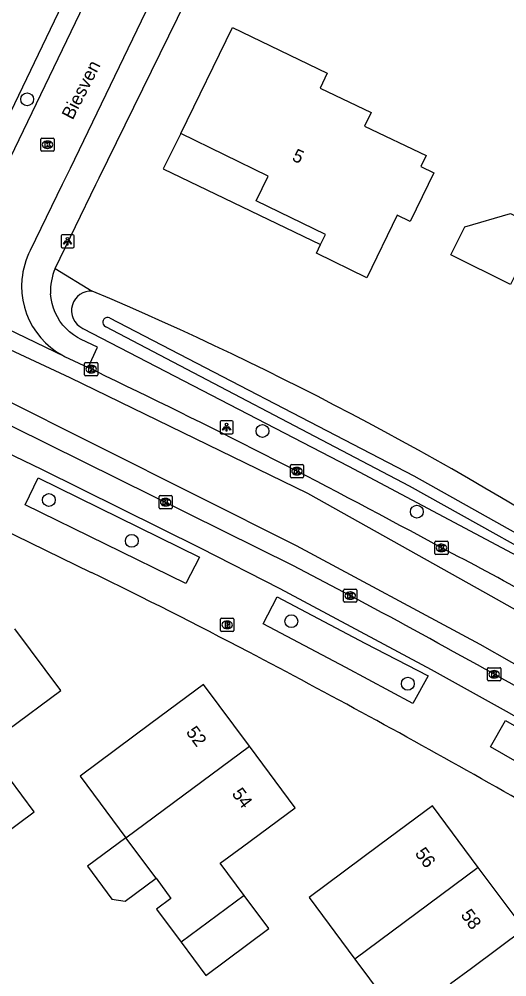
# Model space of a CAD drawing. Extents: x 163427 to 164190, y 380331 to 381641.
# Drawn here: x 163745.4 to 163782.5, y 381439.7 to 381512.6 of the extents above; entities that cross this region are included whole.
import ezdxf

# ---------------------------------------------------------------- set-up
doc = ezdxf.new("R2010")
doc.units = 0
for name, color, linetype in [('IMGEO_Boom', 7, 'Continuous'), ('IMGEO_Brandkraan', 7, 'Continuous'), ('IMGEO_Erf', 7, 'Continuous'), ('IMGEO_Groenvoorziening', 7, 'Continuous'), ('IMGEO_Kolk', 7, 'Continuous'), ('IMGEO_Lichtpunt', 7, 'Continuous'), ('IMGEO_Openbare_ruimte_label', 7, 'Continuous'), ('IMGEO_Pand', 7, 'Continuous'), ('IMGEO_Pand_nummerreeks', 7, 'Continuous'), ('IMGEO_Pand_overbouw', 7, 'Continuous'), ('IMGEO_Rijbaan_lokaal_gesloten', 7, 'Continuous'), ('IMGEO_Rijbaan_lokaal_open', 7, 'Continuous'), ('IMGEO_Voetpad_open', 7, 'Continuous'), ('IMGEO_Waterloop', 7, 'Continuous')]:
    doc.layers.add(name, color=color, linetype=linetype)

msp = doc.modelspace()

# ---------------------------------------------------------------- linework, layer by layer
at = {"layer": 'IMGEO_Boom'}
for centre in [(163745.966, 381506.482), (163763.886, 381481.228), (163747.622, 381475.986), (163775.647, 381475.092), (163753.933, 381472.871), (163766.089, 381466.756), (163774.959, 381461.993)]:
    msp.add_circle(centre, 0.489, dxfattribs=at)
at = {"layer": 'IMGEO_Brandkraan'}
for p, q in [((163760.702, 381466.052), (163760.702, 381466.904)), ((163760.777, 381466.978), (163761.629, 381466.978)), ((163761.19, 381466.758), (163761.215, 381466.758)), ((163761.703, 381466.904), (163761.703, 381466.052)), ((163761.629, 381465.978), (163760.777, 381465.978)), ((163761.213, 381466.198), (163761.188, 381466.198))]:
    msp.add_line(p, q, dxfattribs=at)
for points in [[(163760.702, 381466.052), (163760.702, 381466.904)], [(163760.777, 381466.978), (163761.629, 381466.978)], [(163761.05, 381466.678), (163761.05, 381466.278), (163761.263, 381466.278)], [(163761.281, 381466.678), (163761.05, 381466.678)], [(163761.229, 381466.597), (163761.175, 381466.597), (163761.175, 381466.521)], [(163761.703, 381466.904), (163761.703, 381466.052)], [(163761.629, 381465.978), (163760.777, 381465.978)], [(163761.175, 381466.521), (163761.228, 381466.521)], [(163761.237, 381466.445), (163761.175, 381466.445), (163761.175, 381466.364)], [(163761.175, 381466.364), (163761.237, 381466.364)]]:
    msp.add_lwpolyline(points, dxfattribs=at)
for centre, radius, start, end in [((163760.779, 381466.902), 0.0765, 91.55205, 178.44795), ((163760.779, 381466.902), 0.0765, 91.55205, 178.44795), ((163761.23, 381466.559), 0.0379, 267.82845, 90.93552), ((163761.285, 381466.533), 0.145, 59.4692, 91.53667), ((163761.31, 381466.58), 0.0922, 285.51372, 58.15012), ((163761.627, 381466.902), 0.0765, 1.55205, 88.44795), ((163761.627, 381466.902), 0.0765, 1.55205, 88.44795), ((163760.779, 381466.054), 0.0765, 181.55205, 268.44795), ((163760.779, 381466.054), 0.0765, 181.55205, 268.44795), ((163761.238, 381466.404), 0.0404, 269.87594, 90.50774), ((163761.269, 381466.529), 0.251, 268.66757, 293.53466), ((163761.315, 381466.388), 0.105, 301.31148, 78.98903), ((163761.627, 381466.054), 0.0765, 271.55205, 358.44795), ((163761.627, 381466.054), 0.0765, 271.55205, 358.44795)]:
    msp.add_arc(centre, radius, start, end, dxfattribs=at)
for centre, major_axis, ratio, start_param, end_param in [((163761.189, 381466.478), (-0.387, 0.002), 0.722429, 4.712389, 7.853982), ((163761.214, 381466.478), (-0.39, 0.002), 0.717154, 1.570796, 4.712389)]:
    msp.add_ellipse(centre, major_axis=major_axis, ratio=ratio, start_param=start_param, end_param=end_param, dxfattribs=at)
at = {"layer": 'IMGEO_Erf'}
msp.add_arc((163648.773, 381250.963), 261.688, 56.82507, 67.02228, dxfattribs=at)
at = {"layer": 'IMGEO_Groenvoorziening'}
for points in [[(163748.094, 381493.596), (163750.929, 381491.888)], [(163750.217, 381489.043), (163770.434, 381478.548), (163790.557, 381467.873), (163791.144, 381468.756), (163791.968, 381469.997)]]:
    msp.add_lwpolyline(points, dxfattribs=at)
for centre, radius, start, end in [((163750.847, 381490.382), 1.508, 86.88217, 162.37466), ((163750.823, 381490.394), 1.481, 162.53027, 245.86154)]:
    msp.add_arc(centre, radius, start, end, dxfattribs=at)
at = {"layer": 'IMGEO_Kolk'}
for p, q in [((163747.015, 381502.603), (163747.015, 381503.455)), ((163747.09, 381503.529), (163747.942, 381503.529)), ((163747.503, 381503.309), (163747.528, 381503.309)), ((163748.016, 381503.455), (163748.016, 381502.603)), ((163747.942, 381502.529), (163747.09, 381502.529)), ((163747.526, 381502.749), (163747.501, 381502.749)), ((163750.339, 381485.517), (163750.339, 381486.369)), ((163750.414, 381486.443), (163751.266, 381486.443)), ((163751.34, 381486.369), (163751.34, 381485.517)), ((163750.85, 381485.663), (163750.825, 381485.663)), ((163750.827, 381486.223), (163750.852, 381486.223)), ((163751.266, 381485.443), (163750.414, 381485.443)), ((163766.015, 381477.749), (163766.015, 381478.601)), ((163766.09, 381478.675), (163766.942, 381478.675)), ((163766.503, 381478.455), (163766.528, 381478.455)), ((163767.016, 381478.601), (163767.016, 381477.749)), ((163766.942, 381477.675), (163766.09, 381477.675)), ((163766.526, 381477.895), (163766.501, 381477.895)), ((163756.013, 381475.39), (163756.013, 381476.242)), ((163756.088, 381476.316), (163756.94, 381476.316)), ((163756.501, 381476.096), (163756.526, 381476.096)), ((163757.014, 381476.242), (163757.014, 381475.39)), ((163756.524, 381475.536), (163756.499, 381475.536)), ((163756.94, 381475.316), (163756.088, 381475.316)), ((163777.023, 381471.91), (163777.023, 381472.762)), ((163777.098, 381472.836), (163777.95, 381472.836)), ((163777.511, 381472.616), (163777.536, 381472.616)), ((163778.024, 381472.762), (163778.024, 381471.91)), ((163777.95, 381471.836), (163777.098, 381471.836)), ((163777.534, 381472.056), (163777.509, 381472.056)), ((163770.072, 381468.274), (163770.072, 381469.126)), ((163770.147, 381469.2), (163770.999, 381469.2)), ((163770.56, 381468.98), (163770.585, 381468.98)), ((163771.073, 381469.126), (163771.073, 381468.274)), ((163770.999, 381468.2), (163770.147, 381468.2)), ((163770.583, 381468.42), (163770.558, 381468.42)), ((163781.034, 381462.29), (163781.034, 381463.142)), ((163781.109, 381463.216), (163781.961, 381463.216)), ((163781.522, 381462.996), (163781.547, 381462.996)), ((163782.035, 381463.142), (163782.035, 381462.29)), ((163781.961, 381462.216), (163781.109, 381462.216)), ((163781.545, 381462.436), (163781.52, 381462.436))]:
    msp.add_line(p, q, dxfattribs=at)
for points in [[(163747.015, 381502.603), (163747.015, 381503.455)], [(163747.09, 381503.529), (163747.942, 381503.529)], [(163747.336, 381503.229), (163747.459, 381503.229), (163747.459, 381503.078), (163747.589, 381503.229), (163747.753, 381503.229), (163747.607, 381503.078), (163747.76, 381502.829), (163747.608, 381502.829), (163747.523, 381502.993), (163747.459, 381502.926), (163747.459, 381502.829), (163747.336, 381502.829), (163747.336, 381503.229)], [(163748.016, 381503.455), (163748.016, 381502.603)], [(163747.942, 381502.529), (163747.09, 381502.529)], [(163750.339, 381485.517), (163750.339, 381486.369)], [(163750.414, 381486.443), (163751.266, 381486.443)], [(163751.34, 381486.369), (163751.34, 381485.517)], [(163750.66, 381486.143), (163750.783, 381486.143), (163750.783, 381485.992), (163750.913, 381486.143), (163751.077, 381486.143), (163750.931, 381485.992), (163751.084, 381485.743), (163750.932, 381485.743), (163750.847, 381485.907), (163750.783, 381485.84), (163750.783, 381485.743), (163750.66, 381485.743), (163750.66, 381486.143)], [(163751.266, 381485.443), (163750.414, 381485.443)], [(163766.015, 381477.749), (163766.015, 381478.601)], [(163766.09, 381478.675), (163766.942, 381478.675)], [(163766.336, 381478.375), (163766.459, 381478.375), (163766.459, 381478.224), (163766.589, 381478.375), (163766.753, 381478.375), (163766.607, 381478.224), (163766.76, 381477.975), (163766.608, 381477.975), (163766.523, 381478.139), (163766.459, 381478.072), (163766.459, 381477.975), (163766.336, 381477.975), (163766.336, 381478.375)], [(163767.016, 381478.601), (163767.016, 381477.749)], [(163766.942, 381477.675), (163766.09, 381477.675)], [(163756.013, 381475.39), (163756.013, 381476.242)], [(163756.088, 381476.316), (163756.94, 381476.316)], [(163757.014, 381476.242), (163757.014, 381475.39)], [(163756.334, 381476.016), (163756.457, 381476.016), (163756.457, 381475.865), (163756.587, 381476.016), (163756.751, 381476.016), (163756.605, 381475.865), (163756.758, 381475.616), (163756.606, 381475.616), (163756.521, 381475.78), (163756.457, 381475.713), (163756.457, 381475.616), (163756.334, 381475.616), (163756.334, 381476.016)], [(163756.94, 381475.316), (163756.088, 381475.316)], [(163777.023, 381471.91), (163777.023, 381472.762)], [(163777.098, 381472.836), (163777.95, 381472.836)], [(163777.344, 381472.536), (163777.467, 381472.536), (163777.467, 381472.385), (163777.597, 381472.536), (163777.761, 381472.536), (163777.615, 381472.385), (163777.768, 381472.136), (163777.616, 381472.136), (163777.531, 381472.3), (163777.467, 381472.233), (163777.467, 381472.136), (163777.344, 381472.136), (163777.344, 381472.536)], [(163778.024, 381472.762), (163778.024, 381471.91)], [(163777.95, 381471.836), (163777.098, 381471.836)], [(163770.072, 381468.274), (163770.072, 381469.126)], [(163770.147, 381469.2), (163770.999, 381469.2)], [(163770.393, 381468.9), (163770.516, 381468.9), (163770.516, 381468.749), (163770.646, 381468.9), (163770.81, 381468.9), (163770.664, 381468.749), (163770.817, 381468.5), (163770.665, 381468.5), (163770.58, 381468.664), (163770.516, 381468.597), (163770.516, 381468.5), (163770.393, 381468.5), (163770.393, 381468.9)], [(163771.073, 381469.126), (163771.073, 381468.274)], [(163770.999, 381468.2), (163770.147, 381468.2)], [(163781.034, 381462.29), (163781.034, 381463.142)], [(163781.109, 381463.216), (163781.961, 381463.216)], [(163782.035, 381463.142), (163782.035, 381462.29)], [(163781.961, 381462.216), (163781.109, 381462.216)], [(163781.355, 381462.916), (163781.478, 381462.916), (163781.478, 381462.765), (163781.608, 381462.916), (163781.772, 381462.916), (163781.626, 381462.765), (163781.779, 381462.516), (163781.627, 381462.516), (163781.542, 381462.68), (163781.478, 381462.613), (163781.478, 381462.516), (163781.355, 381462.516), (163781.355, 381462.916)]]:
    msp.add_lwpolyline(points, dxfattribs=at)
for centre, start, end in [((163747.092, 381503.453), 91.55205, 178.44795), ((163747.092, 381503.453), 91.55205, 178.44795), ((163747.94, 381503.453), 1.55205, 88.44795), ((163747.94, 381503.453), 1.55205, 88.44795), ((163747.092, 381502.605), 181.55205, 268.44795), ((163747.092, 381502.605), 181.55205, 268.44795), ((163747.94, 381502.605), 271.55205, 358.44795), ((163747.94, 381502.605), 271.55205, 358.44795), ((163750.416, 381486.367), 91.55205, 178.44795), ((163750.416, 381486.367), 91.55205, 178.44795), ((163751.264, 381486.367), 1.55205, 88.44795), ((163751.264, 381486.367), 1.55205, 88.44795), ((163750.416, 381485.519), 181.55205, 268.44795), ((163750.416, 381485.519), 181.55205, 268.44795), ((163751.264, 381485.519), 271.55205, 358.44795), ((163751.264, 381485.519), 271.55205, 358.44795), ((163766.092, 381478.599), 91.55205, 178.44795), ((163766.092, 381478.599), 91.55205, 178.44795), ((163766.94, 381478.599), 1.55205, 88.44795), ((163766.94, 381478.599), 1.55205, 88.44795), ((163766.092, 381477.751), 181.55205, 268.44795), ((163766.092, 381477.751), 181.55205, 268.44795), ((163766.94, 381477.751), 271.55205, 358.44795), ((163766.94, 381477.751), 271.55205, 358.44795), ((163756.09, 381476.24), 91.55205, 178.44795), ((163756.09, 381476.24), 91.55205, 178.44795), ((163756.938, 381476.24), 1.55205, 88.44795), ((163756.938, 381476.24), 1.55205, 88.44795), ((163756.09, 381475.392), 181.55205, 268.44795), ((163756.09, 381475.392), 181.55205, 268.44795), ((163756.938, 381475.392), 271.55205, 358.44795), ((163756.938, 381475.392), 271.55205, 358.44795), ((163777.1, 381472.76), 91.55205, 178.44795), ((163777.1, 381472.76), 91.55205, 178.44795), ((163777.948, 381472.76), 1.55205, 88.44795), ((163777.948, 381472.76), 1.55205, 88.44795), ((163777.1, 381471.912), 181.55205, 268.44795), ((163777.1, 381471.912), 181.55205, 268.44795), ((163777.948, 381471.912), 271.55205, 358.44795), ((163777.948, 381471.912), 271.55205, 358.44795), ((163770.149, 381469.124), 91.55205, 178.44795), ((163770.149, 381469.124), 91.55205, 178.44795), ((163770.997, 381469.124), 1.55205, 88.44795), ((163770.997, 381469.124), 1.55205, 88.44795), ((163770.149, 381468.276), 181.55205, 268.44795), ((163770.149, 381468.276), 181.55205, 268.44795), ((163770.997, 381468.276), 271.55205, 358.44795), ((163770.997, 381468.276), 271.55205, 358.44795), ((163781.111, 381463.14), 91.55205, 178.44795), ((163781.111, 381463.14), 91.55205, 178.44795), ((163781.959, 381463.14), 1.55205, 88.44795), ((163781.959, 381463.14), 1.55205, 88.44795), ((163781.111, 381462.292), 181.55205, 268.44795), ((163781.111, 381462.292), 181.55205, 268.44795), ((163781.959, 381462.292), 271.55205, 358.44795), ((163781.959, 381462.292), 271.55205, 358.44795)]:
    msp.add_arc(centre, 0.0765, start, end, dxfattribs=at)
for centre, major_axis, ratio, start_param, end_param in [((163747.502, 381503.029), (-0.387, 0.002), 0.722429, 4.712389, 7.853982), ((163747.527, 381503.029), (-0.39, 0.002), 0.717154, 1.570796, 4.712389), ((163750.826, 381485.943), (-0.387, 0.002), 0.722429, 4.712389, 7.853982), ((163750.851, 381485.943), (-0.39, 0.002), 0.717154, 1.570796, 4.712389), ((163766.502, 381478.175), (-0.387, 0.002), 0.722429, 4.712389, 7.853982), ((163766.527, 381478.175), (-0.39, 0.002), 0.717154, 1.570796, 4.712389), ((163756.5, 381475.816), (-0.387, 0.002), 0.722429, 4.712389, 7.853982), ((163756.525, 381475.816), (-0.39, 0.002), 0.717154, 1.570796, 4.712389), ((163777.51, 381472.336), (-0.387, 0.002), 0.722429, 4.712389, 7.853982), ((163777.535, 381472.336), (-0.39, 0.002), 0.717154, 1.570796, 4.712389), ((163770.559, 381468.7), (-0.387, 0.002), 0.722429, 4.712389, 7.853982), ((163770.584, 381468.7), (-0.39, 0.002), 0.717154, 1.570796, 4.712389), ((163781.521, 381462.716), (-0.387, 0.002), 0.722429, 4.712389, 7.853982), ((163781.546, 381462.716), (-0.39, 0.002), 0.717154, 1.570796, 4.712389)]:
    msp.add_ellipse(centre, major_axis=major_axis, ratio=ratio, start_param=start_param, end_param=end_param, dxfattribs=at)
at = {"layer": 'IMGEO_Lichtpunt'}
for p, q in [((163748.544, 381496.079), (163748.544, 381495.272)), ((163748.544, 381496.079), (163748.544, 381495.272)), ((163749.446, 381496.174), (163748.638, 381496.174)), ((163749.446, 381496.174), (163748.638, 381496.174)), ((163749.54, 381495.272), (163749.54, 381496.079)), ((163749.54, 381495.272), (163749.54, 381496.079)), ((163748.638, 381495.178), (163749.446, 381495.178)), ((163748.638, 381495.178), (163749.446, 381495.178)), ((163760.659, 381481.925), (163760.659, 381481.118)), ((163760.659, 381481.925), (163760.659, 381481.118)), ((163761.561, 381482.02), (163760.753, 381482.02)), ((163761.561, 381482.02), (163760.753, 381482.02)), ((163761.655, 381481.118), (163761.655, 381481.925)), ((163761.655, 381481.118), (163761.655, 381481.925)), ((163760.753, 381481.024), (163761.561, 381481.024)), ((163760.753, 381481.024), (163761.561, 381481.024))]:
    msp.add_line(p, q, dxfattribs=at)
for points in [[(163748.918, 381495.743), (163748.957, 381495.715), (163748.769, 381495.453), (163748.731, 381495.48), (163748.918, 381495.743)], [(163749.02, 381495.695), (163749.067, 381495.695), (163749.067, 381495.373), (163749.02, 381495.373), (163749.02, 381495.695)], [(163749.13, 381495.715), (163749.168, 381495.742), (163749.355, 381495.48), (163749.316, 381495.452), (163749.13, 381495.715)], [(163761.033, 381481.589), (163761.072, 381481.561), (163760.884, 381481.299), (163760.846, 381481.326), (163761.033, 381481.589)], [(163761.135, 381481.541), (163761.182, 381481.541), (163761.182, 381481.219), (163761.135, 381481.219), (163761.135, 381481.541)], [(163761.245, 381481.561), (163761.283, 381481.588), (163761.47, 381481.326), (163761.431, 381481.298), (163761.245, 381481.561)]]:
    msp.add_lwpolyline(points, dxfattribs=at)
for centre in [(163749.043, 381495.877), (163761.158, 381481.723)]:
    msp.add_circle(centre, 0.0994, dxfattribs=at)
for centre, start, end in [((163748.638, 381496.079), 90, 180), ((163748.638, 381496.079), 90, 180), ((163749.446, 381496.079), 0, 90), ((163749.446, 381496.079), 0, 90), ((163748.638, 381495.272), 180, 270), ((163748.638, 381495.272), 180, 270), ((163749.446, 381495.272), 270, 0), ((163749.446, 381495.272), 270, 360), ((163760.753, 381481.925), 90, 180), ((163760.753, 381481.925), 90, 180), ((163761.561, 381481.925), 0, 90), ((163761.561, 381481.925), 0, 90), ((163760.753, 381481.118), 180, 270), ((163760.753, 381481.118), 180, 270), ((163761.561, 381481.118), 270, 0), ((163761.561, 381481.118), 270, 360)]:
    msp.add_arc(centre, 0.0946, start, end, dxfattribs=at)
at = {"layer": 'IMGEO_Pand'}
for points in [[(163771.846, 381492.891), (163768.002, 381494.78), (163768.316, 381495.43), (163768.679, 381496.182), (163763.41, 381498.748), (163764.329, 381500.636), (163757.668, 381503.881), (163761.598, 381511.951), (163768.828, 381508.473), (163768.288, 381507.343), (163772.167, 381505.491), (163771.659, 381504.45), (163776.349, 381502.199), (163775.94, 381501.374), (163776.927, 381500.885), (163776.501, 381500), (163775.149, 381497.192), (163774.155, 381497.672), (163771.846, 381492.891)], [(163782.774, 381492.375), (163778.245, 381494.64), (163779.308, 381496.765), (163782.779, 381497.788), (163784.941, 381496.707), (163782.774, 381492.375)], [(163744.631, 381454.777), (163742.81, 381457.24), (163744.503, 381458.494), (163748.52, 381461.47), (163745.038, 381466.162)], [(163762.89, 381457.25), (163759.4, 381461.94), (163755.388, 381458.958), (163750.01, 381454.96), (163753.489, 381450.276)], [(163753.489, 381450.276), (163762.89, 381457.25)], [(163762.495, 381445.878), (163760.678, 381448.324), (163762.367, 381449.579), (163766.38, 381452.56), (163762.89, 381457.25)], [(163739.815, 381451.206), (163741.689, 381448.68), (163746.5, 381452.25), (163744.631, 381454.777)], [(163780.328, 381448.016), (163776.84, 381452.71), (163772.828, 381449.728), (163767.45, 381445.73), (163770.934, 381441.04)], [(163753.489, 381450.276), (163750.558, 381448.102), (163752.42, 381445.592), (163753.439, 381445.445), (163755.785, 381447.185)], [(163755.785, 381447.185), (163753.489, 381450.276)], [(163780.328, 381448.016), (163770.934, 381441.04)], [(163780.023, 381436.723), (163778.207, 381439.168), (163779.797, 381440.349), (163783.81, 381443.33), (163780.328, 381448.016)], [(163755.785, 381447.185), (163756.921, 381445.657), (163755.815, 381444.835), (163757.692, 381442.309)], [(163757.692, 381442.309), (163759.568, 381439.783), (163764.372, 381443.352), (163762.495, 381445.878)], [(163762.495, 381445.878), (163757.692, 381442.309)], [(163770.934, 381441.04), (163774.351, 381436.44), (163773.325, 381435.678), (163775.203, 381433.15)]]:
    msp.add_lwpolyline(points, dxfattribs=at)
at = {"layer": 'IMGEO_Pand_overbouw'}
msp.add_lwpolyline([(163757.668, 381503.881), (163756.329, 381501.196), (163768.316, 381495.43), (163768.679, 381496.182), (163763.41, 381498.748), (163764.329, 381500.636)], close=True, dxfattribs=at)
at = {"layer": 'IMGEO_Rijbaan_lokaal_gesloten'}
for points in [[(163713.873, 381501.243), (163733.236, 381492.736), (163749.22, 381485.298), (163767.31, 381476.496), (163780.878, 381468.904), (163793.021, 381462.086), (163801.914, 381456.926), (163805.316, 381454.777), (163822.941, 381443.637), (163833.227, 381436.556), (163841.848, 381430.533), (163854.116, 381421.564)], [(163712.408, 381497.746), (163724.81, 381492.736), (163743.644, 381483.934), (163766.443, 381472.53), (163780.444, 381464.999), (163785.277, 381462.271), (163803.377, 381451.63), (163810.77, 381447.112), (163827.662, 381436.066), (163844.931, 381423.887), (163862.01, 381410.858), (163868.144, 381405.949), (163877.464, 381398.208), (163891.264, 381386.878), (163901.361, 381378.381), (163902.433, 381377.241), (163901.472, 381376.366)], [(163748.812, 381486.917), (163733.515, 381494.261)], [(163728.48, 381489.431), (163742.203, 381482.882), (163766.164, 381471.027), (163770.574, 381468.713)], [(163748.812, 381486.917), (163750.6, 381486.057)], [(163751.927, 381485.409), (163750.857, 381485.961), (163750.6, 381486.057)]]:
    msp.add_lwpolyline(points, dxfattribs=at)
for centre, radius, start, end in [((163526.945, 381013.338), 522.942, 61.36913, 64.5182), ((163658.879, 381242.229), 258.892, 59.28552, 62.72489), ((163344.636, 380676.214), 899.71, 60.338897, 61.743637)]:
    msp.add_arc(centre, radius, start, end, dxfattribs=at)
at = {"layer": 'IMGEO_Rijbaan_lokaal_open'}
for points in [[(163742.315, 381497.297), (163743.1, 381498.851), (163743.604, 381499.848), (163743.677, 381500), (163756.899, 381527.435)], [(163760.744, 381525.086), (163749.235, 381501.225), (163748.64, 381500), (163746.201, 381494.982)], [(163745.567, 381492.794), (163745.542, 381492.259), (163745.566, 381491.725), (163745.636, 381491.194), (163745.754, 381490.672), (163745.919, 381490.162), (163746.128, 381489.67), (163746.38, 381489.197), (163746.673, 381488.75), (163747.006, 381488.33), (163747.374, 381487.942), (163747.776, 381487.588), (163748.207, 381487.271), (163748.665, 381486.994), (163748.812, 381486.917)]]:
    msp.add_lwpolyline(points, dxfattribs=at)
msp.add_arc((163751.537, 381492.25), 5.995, 152.8875, 174.7933, dxfattribs=at)
at = {"layer": 'IMGEO_Voetpad_open'}
for points in [[(163755.555, 381528.169), (163742.257, 381500.486), (163742.008, 381500)], [(163748.094, 381493.596), (163751.203, 381500), (163751.446, 381500.501), (163763.393, 381524.85)], [(163750.6, 381486.057), (163751.32, 381487.615), (163750.075, 381488.2), (163749.803, 381488.345), (163749.491, 381488.546), (163749.199, 381488.774), (163748.928, 381489.027), (163748.68, 381489.303), (163748.459, 381489.601), (163748.264, 381489.917), (163748.099, 381490.249), (163747.964, 381490.594), (163747.861, 381490.95), (163747.789, 381491.314), (163747.751, 381491.683)], [(163799.845, 381449.729), (163793.982, 381453.254), (163793.115, 381453.768), (163792.247, 381454.28), (163782.711, 381459.759), (163776.754, 381463.062), (163765.24, 381469.221), (163759.164, 381472.317), (163747.09, 381478.292), (163740.938, 381481.248)], [(163729.966, 381480.543), (163741.52, 381475.007), (163750.853, 381470.467)], [(163758.061, 381469.622), (163745.812, 381475.626), (163746.801, 381477.662), (163759.085, 381471.629), (163758.061, 381469.622)], [(163770.243, 381463.226), (163763.951, 381466.549), (163765.004, 381468.6), (163771.674, 381465.073), (163776.499, 381462.586), (163775.348, 381460.485), (163770.243, 381463.226)], [(163792.566, 381450.689), (163781.265, 381457.187), (163782.392, 381459.206), (163793.724, 381452.667), (163792.566, 381450.689)]]:
    msp.add_lwpolyline(points, dxfattribs=at)
for centre, radius, start, end in [((163751.895, 381491.927), 4.151, 156.29748, 183.37233), ((163555.961, 381070.196), 445.197, 62.31188, 64.03851), ((163450.858, 380869.639), 671.624, 60.542611, 62.322392), ((163514.222, 380980.216), 544.183, 58.44928, 60.6261)]:
    msp.add_arc(centre, radius, start, end, dxfattribs=at)
at = {"layer": 'IMGEO_Waterloop'}
for points in [[(163752.239, 381489.857), (163775.409, 381477.832), (163789.857, 381469.734)], [(163789.385, 381469.057), (163775.086, 381477.031), (163751.952, 381489.159)]]:
    msp.add_lwpolyline(points, dxfattribs=at)
msp.add_arc((163752.094, 381489.509), 0.377, 67.3804, 247.91714, dxfattribs=at)

# ---------------------------------------------------------------- texts
at = {"layer": 'IMGEO_Openbare_ruimte_label'}
msp.add_text('Biesven', height=1, rotation=63.12746, dxfattribs=at).set_placement((163749.432, 381504.865))
at = {"layer": 'IMGEO_Pand_nummerreeks'}
for s, rotation, p in [('5', 335.34563, (163766.071, 381501.859)), ('52', 306.65428, (163758.018, 381458.302)), ('54', 306.6519, (163761.51, 381453.61)), ('56', 306.61495, (163775.457, 381449.071)), ('58', 306.61495, (163778.944, 381444.379))]:
    msp.add_text(s, height=1, rotation=rotation, dxfattribs=at).set_placement(p)

doc.saveas('drawing.dxf')
